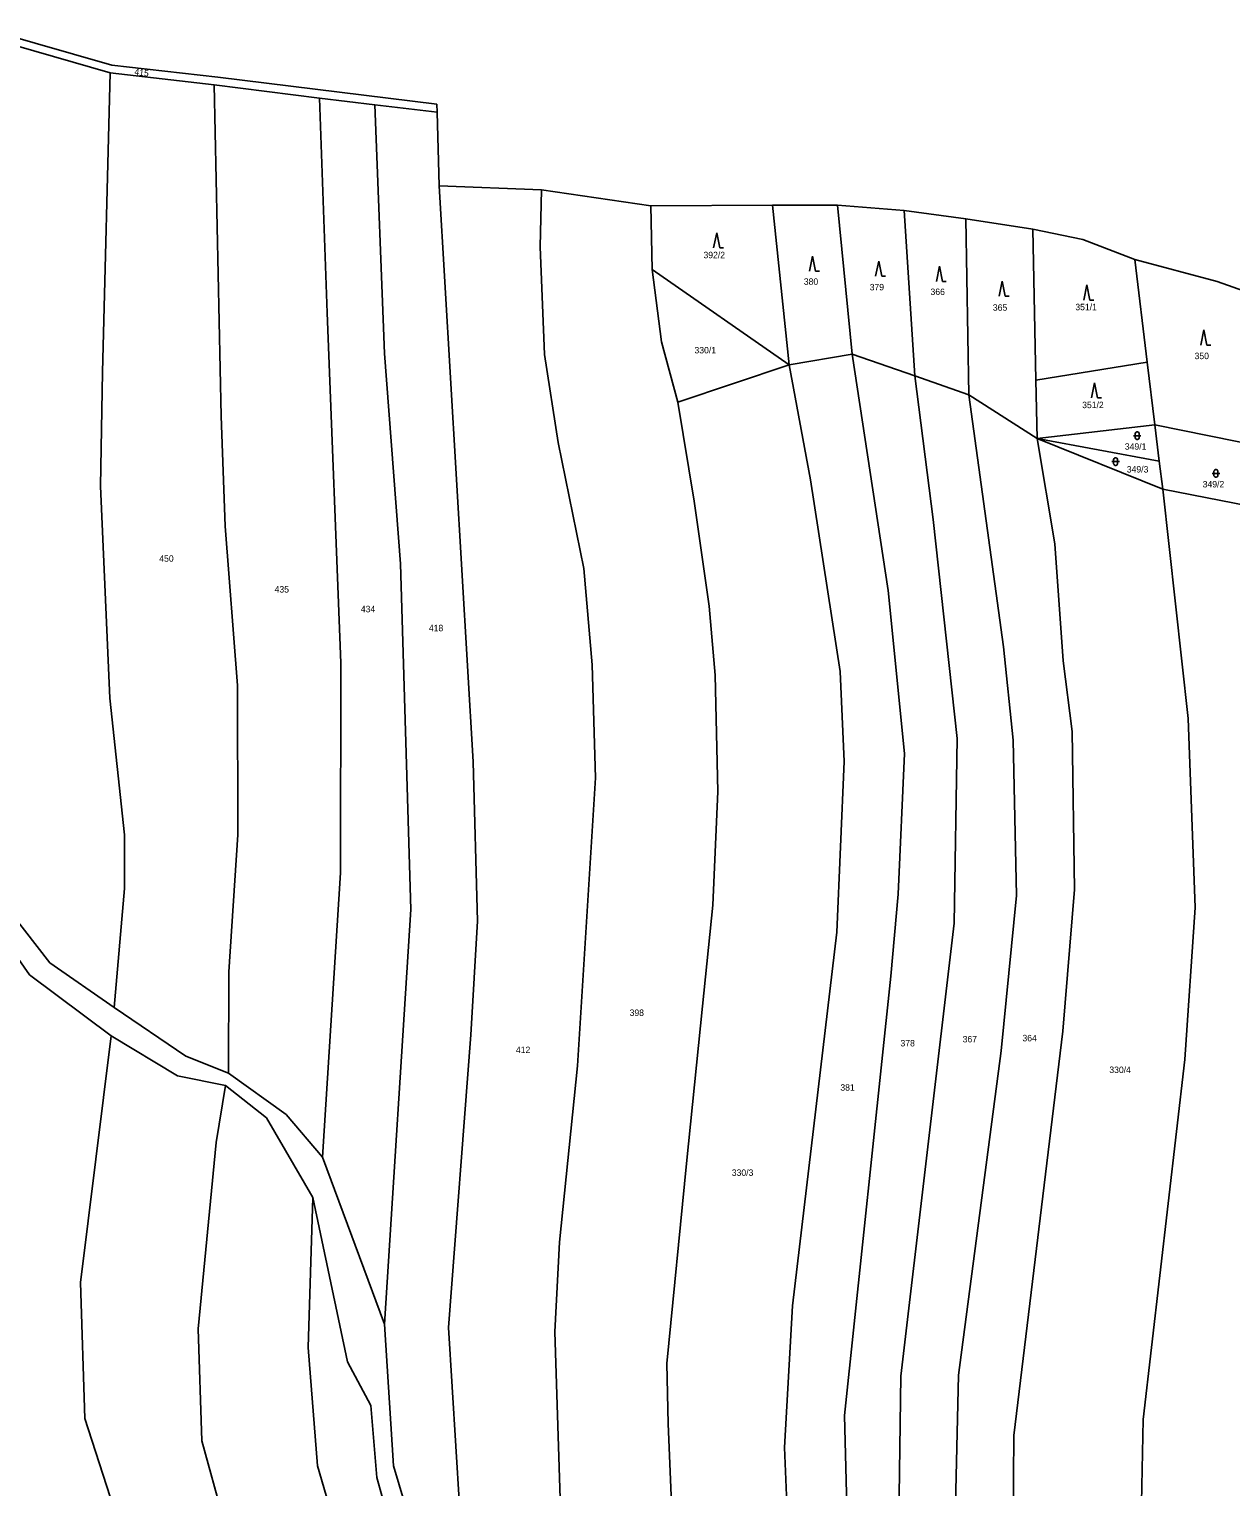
# Model space of a CAD drawing. Extents: x -794142 to -791199, y -1109267 to -1105626.
# Drawn here: x -792667.2 to -792350.1, y -1106886 to -1106501.4 of the extents above; entities that cross this region are included whole.
import ezdxf

# ---------------------------------------------------------------- set-up
doc = ezdxf.new("R2010")
doc.units = 0
for name, color, linetype in [('Vrstva 1', 7, 'Continuous'), ('Vrstva 14', 7, 'Continuous'), ('Vrstva 23', 7, 'Continuous')]:
    doc.layers.add(name, color=color, linetype=linetype)

msp = doc.modelspace()

# ---------------------------------------------------------------- linework, layer by layer
at = {"layer": 'Vrstva 1'}
for p, q in [((-792645.42, -1106510.92), (-792678.57, -1106501.45)), ((-792678, -1106503.76), (-792645.84, -1106512.96)), ((-792617.44, -1106514.13), (-792645.42, -1106510.92)), ((-792645.84, -1106512.96), (-792647.88, -1106591.9)), ((-792645.84, -1106512.96), (-792618.37, -1106516.18)), ((-792617.44, -1106514.13), (-792559.63, -1106521.2)), ((-792618.37, -1106516.18), (-792590.65, -1106519.69)), ((-792618.37, -1106516.18), (-792616.53, -1106603.51)), ((-792590.65, -1106519.69), (-792576, -1106521.42)), ((-792590.65, -1106519.69), (-792588.58, -1106576.31)), ((-792576, -1106521.42), (-792559.57, -1106523.33)), ((-792576, -1106521.42), (-792573.44, -1106587.02)), ((-792559.57, -1106523.33), (-792559.63, -1106521.2)), ((-792559.04, -1106542.78), (-792559.57, -1106523.33)), ((-792532.01, -1106543.8), (-792559.04, -1106542.78)), ((-792559.04, -1106542.78), (-792550.08, -1106694.74)), ((-792532.01, -1106543.8), (-792532.35, -1106558.85)), ((-792503.15, -1106548.03), (-792532.01, -1106543.8)), ((-792471.09, -1106547.88), (-792503.15, -1106548.03)), ((-792503.15, -1106548.03), (-792502.81, -1106564.86)), ((-792453.9, -1106547.88), (-792471.09, -1106547.88)), ((-792466.63, -1106589.96), (-792471.09, -1106547.88)), ((-792436.29, -1106549.28), (-792453.9, -1106547.88)), ((-792450.05, -1106587.16), (-792453.9, -1106547.88)), ((-792420.05, -1106551.52), (-792436.29, -1106549.28)), ((-792433.49, -1106592.87), (-792436.29, -1106549.28)), ((-792402.36, -1106554.21), (-792420.05, -1106551.52)), ((-792419.27, -1106597.92), (-792420.05, -1106551.52)), ((-792401.55, -1106594.04), (-792402.36, -1106554.21)), ((-792389.12, -1106556.92), (-792402.36, -1106554.21)), ((-792375.45, -1106562.17), (-792389.12, -1106556.92)), ((-792532.35, -1106558.85), (-792531.2, -1106587.27)), ((-792502.81, -1106564.86), (-792466.63, -1106589.96)), ((-792502.81, -1106564.86), (-792500.34, -1106583.95)), ((-792353.7, -1106568), (-792375.45, -1106562.17)), ((-792375.45, -1106562.17), (-792372.18, -1106589.27)), ((-792342.56, -1106571.94), (-792353.7, -1106568)), ((-792588.58, -1106576.31), (-792584.98, -1106668.58)), ((-792500.34, -1106583.95), (-792496.02, -1106599.82)), ((-792573.44, -1106587.02), (-792569.22, -1106642.49)), ((-792531.2, -1106587.27), (-792527.6, -1106610.48)), ((-792466.63, -1106589.96), (-792450.05, -1106587.16)), ((-792450.05, -1106587.16), (-792433.49, -1106592.87)), ((-792450.05, -1106587.16), (-792440.5, -1106649.56)), ((-792647.88, -1106591.9), (-792648.43, -1106621.99)), ((-792496.02, -1106599.82), (-792466.63, -1106589.96)), ((-792466.63, -1106589.96), (-792460.98, -1106620.37)), ((-792401.55, -1106594.04), (-792372.18, -1106589.27)), ((-792372.18, -1106589.27), (-792370.18, -1106605.87)), ((-792433.49, -1106592.87), (-792428.69, -1106630.81)), ((-792433.49, -1106592.87), (-792419.27, -1106597.92)), ((-792401.24, -1106609.46), (-792401.55, -1106594.04)), ((-792496.02, -1106599.82), (-792491.7, -1106625.93)), ((-792419.27, -1106597.92), (-792401.24, -1106609.46)), ((-792419.27, -1106597.92), (-792410.09, -1106664.43)), ((-792616.53, -1106603.51), (-792615.52, -1106632.56)), ((-792370.18, -1106605.87), (-792401.24, -1106609.46)), ((-792370.18, -1106605.87), (-792368.99, -1106615.38)), ((-792340.28, -1106611.92), (-792370.18, -1106605.87)), ((-792527.6, -1106610.48), (-792520.82, -1106643.73)), ((-792401.24, -1106609.46), (-792368.06, -1106622.79)), ((-792401.24, -1106609.46), (-792368.99, -1106615.38)), ((-792401.24, -1106609.46), (-792396.57, -1106637.2)), ((-792368.99, -1106615.38), (-792368.06, -1106622.79)), ((-792648.43, -1106621.99), (-792645.93, -1106677.92)), ((-792460.98, -1106620.37), (-792453.19, -1106670.94)), ((-792368.06, -1106622.79), (-792361.35, -1106683.33)), ((-792368.06, -1106622.79), (-792338.6, -1106628.51)), ((-792491.7, -1106625.93), (-792487.8, -1106653.63)), ((-792428.69, -1106630.81), (-792422.35, -1106688.61)), ((-792615.52, -1106632.56), (-792612.24, -1106674.61)), ((-792396.57, -1106637.2), (-792394.37, -1106668.04)), ((-792569.22, -1106642.49), (-792566.54, -1106733.71)), ((-792520.82, -1106643.73), (-792518.66, -1106669.11)), ((-792440.5, -1106649.56), (-792436.18, -1106692.55)), ((-792487.8, -1106653.63), (-792486.22, -1106671.84)), ((-792410.09, -1106664.43), (-792407.49, -1106689)), ((-792584.98, -1106668.58), (-792585.05, -1106724.03)), ((-792518.66, -1106669.11), (-792517.79, -1106698.97)), ((-792394.37, -1106668.04), (-792391.96, -1106686.72)), ((-792485.5, -1106702.55), (-792486.22, -1106671.84)), ((-792453.19, -1106670.94), (-792452.18, -1106694.6)), ((-792612.24, -1106674.61), (-792612.16, -1106713.99)), ((-792645.93, -1106677.92), (-792642.09, -1106713.97)), ((-792361.35, -1106683.33), (-792359.48, -1106733.14)), ((-792422.35, -1106688.61), (-792423.07, -1106737.25)), ((-792391.96, -1106686.72), (-792391.38, -1106728.43)), ((-792436.18, -1106692.55), (-792437.92, -1106729.65)), ((-792407.49, -1106689), (-792406.63, -1106729.97)), ((-792550.08, -1106694.74), (-792548.93, -1106736.72)), ((-792452.18, -1106694.6), (-792454.06, -1106739.64)), ((-792517.79, -1106698.97), (-792522.55, -1106774.91)), ((-792486.8, -1106732.51), (-792485.5, -1106702.55)), ((-792642.09, -1106713.97), (-792642.09, -1106728.11)), ((-792612.16, -1106713.99), (-792614.54, -1106750.09)), ((-792667.18, -1106750.92), (-792683.68, -1106727.25)), ((-792678.93, -1106725.7), (-792661.8, -1106747.76)), ((-792585.05, -1106724.03), (-792589.84, -1106799.05)), ((-792642.09, -1106728.11), (-792644.78, -1106759.5)), ((-792437.92, -1106729.65), (-792439.78, -1106751.25)), ((-792406.63, -1106729.97), (-792410.67, -1106770.94)), ((-792391.38, -1106728.43), (-792394.41, -1106765.74)), ((-792566.54, -1106733.71), (-792573.45, -1106843.03)), ((-792489.54, -1106759.18), (-792486.8, -1106732.51)), ((-792359.48, -1106733.14), (-792362.22, -1106773.25)), ((-792548.93, -1106736.72), (-792550.66, -1106766.72)), ((-792423.07, -1106737.25), (-792437.2, -1106856.77)), ((-792454.06, -1106739.64), (-792465.74, -1106838.21)), ((-792661.8, -1106747.76), (-792644.78, -1106759.5)), ((-792614.54, -1106750.09), (-792614.63, -1106776.89)), ((-792645.59, -1106767.01), (-792667.18, -1106750.92)), ((-792439.78, -1106751.25), (-792452.04, -1106867.18)), ((-792644.78, -1106759.5), (-792625.93, -1106772.34)), ((-792489.54, -1106759.18), (-792493.72, -1106800.67)), ((-792407.39, -1106872.47), (-792394.41, -1106765.74)), ((-792645.59, -1106767.01), (-792653.66, -1106832.06)), ((-792628.05, -1106777.6), (-792645.59, -1106767.01)), ((-792550.66, -1106766.72), (-792556.57, -1106843.92)), ((-792625.93, -1106772.34), (-792614.63, -1106776.89)), ((-792421.94, -1106856.53), (-792410.67, -1106770.94)), ((-792373.2, -1106868.21), (-792362.22, -1106773.25)), ((-792614.63, -1106776.89), (-792599.37, -1106787.75)), ((-792522.55, -1106774.91), (-792527.31, -1106821.45)), ((-792615.39, -1106780.1), (-792628.05, -1106777.6)), ((-792617.92, -1106795.15), (-792615.39, -1106780.1)), ((-792604.57, -1106788.65), (-792615.39, -1106780.1)), ((-792592.33, -1106809.63), (-792604.57, -1106788.65)), ((-792599.37, -1106787.75), (-792589.84, -1106799.05)), ((-792622.66, -1106844.32), (-792617.92, -1106795.15)), ((-792589.84, -1106799.05), (-792573.45, -1106843.03)), ((-792498.91, -1106853.42), (-792493.72, -1106800.67)), ((-792593.61, -1106849.19), (-792592.33, -1106809.63)), ((-792583.19, -1106853.03), (-792592.33, -1106809.63)), ((-792527.31, -1106821.45), (-792528.46, -1106845.11)), ((-792653.66, -1106832.06), (-792652.58, -1106867.91)), ((-792465.74, -1106838.21), (-792467.9, -1106875.61)), ((-792621.67, -1106873.81), (-792622.66, -1106844.32)), ((-792573.45, -1106843.03), (-792571.1, -1106880.45)), ((-792556.57, -1106843.92), (-792553.69, -1106890.89)), ((-792528.46, -1106845.11), (-792526.88, -1106894.81)), ((-792591.11, -1106880.41), (-792593.61, -1106849.19)), ((-792577.08, -1106864.48), (-792583.19, -1106853.03)), ((-792498.62, -1106869.36), (-792498.91, -1106853.42)), ((-792437.2, -1106856.77), (-792437.91, -1106912.01)), ((-792423.24, -1106912.93), (-792421.94, -1106856.53)), ((-792575.51, -1106883.55), (-792577.08, -1106864.48)), ((-792652.58, -1106867.91), (-792638.82, -1106910.38)), ((-792498.62, -1106869.36), (-792497.32, -1106898.5)), ((-792452.04, -1106867.18), (-792450.89, -1106909.94)), ((-792374.07, -1106907.02), (-792373.2, -1106868.21)), ((-792407.68, -1106909.98), (-792407.39, -1106872.47)), ((-792612.48, -1106907.19), (-792621.67, -1106873.81)), ((-792467.9, -1106875.61), (-792466.46, -1106909.37)), ((-792575.3, -1106934.46), (-792591.11, -1106880.41)), ((-792571.1, -1106880.45), (-792555.84, -1106931.48)), ((-792566.17, -1106916.84), (-792575.51, -1106883.55))]:
    msp.add_line(p, q, dxfattribs=at)
at = {"layer": 'Vrstva 23'}
for p, q in [((-792486.58, -1106559.18), (-792485.78, -1106555.18)), ((-792485.78, -1106555.18), (-792484.98, -1106559.18)), ((-792484.98, -1106559.18), (-792483.98, -1106559.18)), ((-792461.27, -1106565.31), (-792460.47, -1106561.31)), ((-792460.47, -1106561.31), (-792459.67, -1106565.31)), ((-792459.67, -1106565.31), (-792458.67, -1106565.31)), ((-792443.83, -1106566.65), (-792443.03, -1106562.65)), ((-792443.03, -1106562.65), (-792442.23, -1106566.65)), ((-792427.81, -1106568), (-792427.01, -1106564)), ((-792427.01, -1106564), (-792426.21, -1106568)), ((-792442.23, -1106566.65), (-792441.23, -1106566.65)), ((-792426.21, -1106568), (-792425.21, -1106568)), ((-792411.23, -1106571.92), (-792410.43, -1106567.92)), ((-792410.43, -1106567.92), (-792409.63, -1106571.92)), ((-792388.87, -1106572.9), (-792388.07, -1106568.9)), ((-792388.07, -1106568.9), (-792387.27, -1106572.9)), ((-792409.63, -1106571.92), (-792408.63, -1106571.92)), ((-792387.27, -1106572.9), (-792386.27, -1106572.9)), ((-792357.99, -1106584.8), (-792357.19, -1106580.8)), ((-792357.19, -1106580.8), (-792356.39, -1106584.8)), ((-792356.39, -1106584.8), (-792355.39, -1106584.8)), ((-792386.85, -1106598.73), (-792386.05, -1106594.73)), ((-792386.05, -1106594.73), (-792385.25, -1106598.73)), ((-792385.25, -1106598.73), (-792384.25, -1106598.73)), ((-792375.3, -1106608.09), (-792375.2, -1106607.89)), ((-792375.3, -1106609.29), (-792375.3, -1106608.09)), ((-792375.2, -1106607.89), (-792375.1, -1106607.79)), ((-792375.1, -1106607.79), (-792374.9, -1106607.69)), ((-792374.9, -1106607.69), (-792374.7, -1106607.69)), ((-792374.7, -1106607.69), (-792374.5, -1106607.79)), ((-792374.5, -1106607.79), (-792374.4, -1106607.89)), ((-792374.4, -1106607.89), (-792374.3, -1106608.09)), ((-792374.3, -1106608.09), (-792374.3, -1106609.29)), ((-792375.8, -1106608.69), (-792373.8, -1106608.69)), ((-792375.2, -1106609.49), (-792375.3, -1106609.29)), ((-792375.1, -1106609.59), (-792375.2, -1106609.49)), ((-792374.9, -1106609.69), (-792375.1, -1106609.59)), ((-792374.7, -1106609.69), (-792374.9, -1106609.69)), ((-792374.5, -1106609.59), (-792374.7, -1106609.69)), ((-792374.4, -1106609.49), (-792374.5, -1106609.59)), ((-792374.3, -1106609.29), (-792374.4, -1106609.49)), ((-792381.51, -1106615.53), (-792379.51, -1106615.53)), ((-792381.01, -1106614.93), (-792380.91, -1106614.73)), ((-792381.01, -1106616.13), (-792381.01, -1106614.93)), ((-792380.91, -1106614.73), (-792380.81, -1106614.63)), ((-792380.81, -1106614.63), (-792380.61, -1106614.53)), ((-792380.61, -1106614.53), (-792380.41, -1106614.53)), ((-792380.41, -1106614.53), (-792380.21, -1106614.63)), ((-792380.21, -1106614.63), (-792380.11, -1106614.73)), ((-792380.11, -1106614.73), (-792380.01, -1106614.93)), ((-792380.01, -1106614.93), (-792380.01, -1106616.13)), ((-792380.91, -1106616.33), (-792381.01, -1106616.13)), ((-792380.81, -1106616.43), (-792380.91, -1106616.33)), ((-792380.61, -1106616.53), (-792380.81, -1106616.43)), ((-792380.41, -1106616.53), (-792380.61, -1106616.53)), ((-792380.21, -1106616.43), (-792380.41, -1106616.53)), ((-792380.11, -1106616.33), (-792380.21, -1106616.43)), ((-792380.01, -1106616.13), (-792380.11, -1106616.33)), ((-792355.03, -1106618.64), (-792353.03, -1106618.64)), ((-792354.53, -1106618.04), (-792354.43, -1106617.84)), ((-792354.53, -1106619.24), (-792354.53, -1106618.04)), ((-792354.43, -1106619.44), (-792354.53, -1106619.24)), ((-792354.43, -1106617.84), (-792354.33, -1106617.74)), ((-792354.33, -1106619.54), (-792354.43, -1106619.44)), ((-792354.33, -1106617.74), (-792354.13, -1106617.64)), ((-792354.13, -1106619.64), (-792354.33, -1106619.54)), ((-792354.13, -1106617.64), (-792353.93, -1106617.64)), ((-792353.93, -1106619.64), (-792354.13, -1106619.64)), ((-792353.93, -1106617.64), (-792353.73, -1106617.74)), ((-792353.73, -1106619.54), (-792353.93, -1106619.64)), ((-792353.73, -1106617.74), (-792353.63, -1106617.84)), ((-792353.63, -1106619.44), (-792353.73, -1106619.54)), ((-792353.63, -1106617.84), (-792353.53, -1106618.04)), ((-792353.53, -1106619.24), (-792353.63, -1106619.44)), ((-792353.53, -1106618.04), (-792353.53, -1106619.24))]:
    msp.add_line(p, q, dxfattribs=at)

# ---------------------------------------------------------------- texts
at = {"layer": 'Vrstva 14'}
msp.add_text('415', height=1.7, rotation=353.03175, dxfattribs=at).set_placement((-792639.537, -1106513.499))
for s, p in [('392/2', (-792489.27, -1106561.88)), ('380', (-792462.786, -1106568.89)), ('379', (-792445.403, -1106570.35)), ('366', (-792429.347, -1106571.58)), ('365', (-792412.893, -1106575.73)), ('351/1', (-792391.123, -1106575.6)), ('330/1', (-792491.642, -1106586.98)), ('350', (-792359.652, -1106588.5)), ('351/2', (-792389.329, -1106601.43)), ('349/1', (-792378.059, -1106612.39)), ('349/3', (-792377.546, -1106618.41)), ('349/2', (-792357.516, -1106622.34)), ('450', (-792632.898, -1106641.94)), ('435', (-792602.459, -1106650.07)), ('434', (-792579.708, -1106655.27)), ('418', (-792561.746, -1106660.28)), ('398', (-792508.767, -1106761.76)), ('378', (-792437.273, -1106769.8)), ('367', (-792420.873, -1106768.73)), ('364', (-792405.083, -1106768.45)), ('412', (-792538.766, -1106771.56)), ('330/4', (-792382.155, -1106776.81)), ('381', (-792453.14, -1106781.47)), ('330/3', (-792481.799, -1106803.95))]:
    msp.add_text(s, height=1.7, dxfattribs=at).set_placement(p)

doc.saveas('drawing.dxf')
